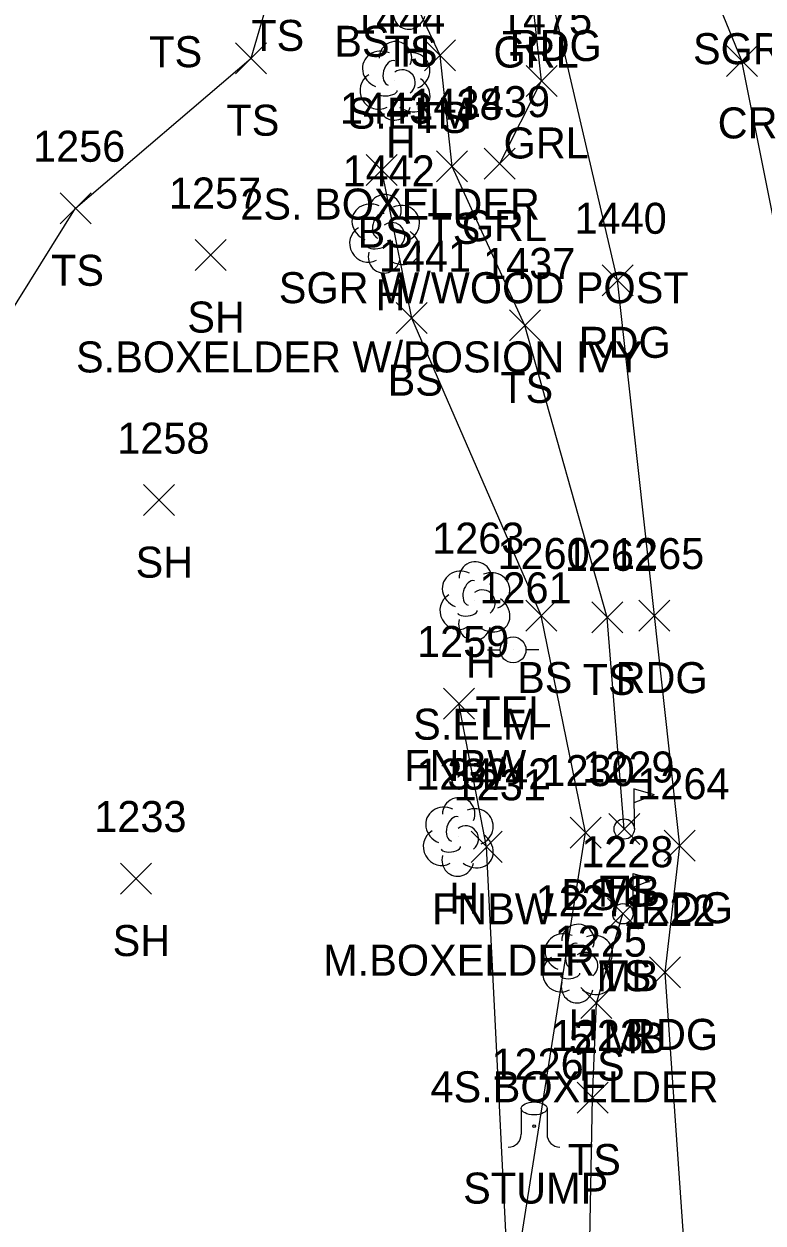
# Model space of a CAD drawing. Extents: x 1459992 to 1461532, y 647785 to 648535.
# Drawn here: x 1461337.5 to 1461385.2, y 648040.8 to 648118.2 of the extents above; entities that cross this region are included whole.
import ezdxf

# ---------------------------------------------------------------- set-up
doc = ezdxf.new("R2010")
doc.units = 0
for name, color, linetype in [('L_A', 7, 'Continuous'), ('L_C', 7, 'Continuous'), ('L_I', 7, 'Continuous'), ('L_TIC', 7, 'Continuous'), ('LELB', 7, 'Continuous'), ('LFNC', 7, 'Continuous'), ('LMB', 7, 'Continuous'), ('LTD', 7, 'Continuous'), ('LTS', 7, 'Continuous'), ('P_A', 7, 'Continuous'), ('P_I', 7, 'Continuous'), ('P_TIC', 7, 'Continuous'), ('PEU', 7, 'Continuous'), ('PRC', 7, 'Continuous'), ('R_A', 7, 'Continuous'), ('R_C', 7, 'Continuous'), ('R_I', 7, 'Continuous'), ('R_TIC', 7, 'Continuous'), ('RGR', 7, 'Continuous'), ('U_A', 7, 'Continuous'), ('U_C', 7, 'Continuous'), ('U_I', 7, 'Continuous'), ('UP', 7, 'Continuous')]:
    doc.layers.add(name, color=color, linetype=linetype)

msp = doc.modelspace()

# ---------------------------------------------------------------- linework, layer by layer
at = {"layer": 'L_TIC'}
for points in [[(1461351.192, 648114.964), (1461353.192, 648116.964)], [(1461353.192, 648114.964), (1461351.192, 648116.964)], [(1461363.389, 648115.139), (1461365.389, 648117.139)], [(1461365.389, 648115.139), (1461363.389, 648117.139)], [(1461359.617, 648107.744), (1461361.617, 648109.744)], [(1461361.617, 648107.744), (1461359.617, 648109.744)], [(1461364.162, 648107.989), (1461366.162, 648109.989)], [(1461366.162, 648107.989), (1461364.162, 648109.989)], [(1461339.87, 648105.284), (1461341.87, 648107.284)], [(1461341.87, 648105.284), (1461339.87, 648107.284)], [(1461348.586, 648102.268), (1461350.586, 648104.268)], [(1461350.586, 648102.268), (1461348.586, 648104.268)], [(1461361.563, 648098.199), (1461363.563, 648100.199)], [(1461363.563, 648098.199), (1461361.563, 648100.199)], [(1461368.859, 648097.73), (1461370.859, 648099.73)], [(1461370.859, 648097.73), (1461368.859, 648099.73)], [(1461345.25, 648086.46), (1461347.25, 648088.46)], [(1461347.25, 648086.46), (1461345.25, 648088.46)], [(1461369.917, 648079.019), (1461371.917, 648081.019)], [(1461371.917, 648079.019), (1461369.917, 648081.019)], [(1461374.178, 648078.9), (1461376.178, 648080.9)], [(1461376.178, 648078.9), (1461374.178, 648080.9)], [(1461364.601, 648073.344), (1461366.601, 648075.344)], [(1461366.601, 648073.344), (1461364.601, 648075.344)], [(1461372.77, 648065.017), (1461374.77, 648067.017)], [(1461374.77, 648065.017), (1461372.77, 648067.017)], [(1461375.265, 648065.249), (1461377.265, 648067.249)], [(1461377.265, 648065.249), (1461375.265, 648067.249)], [(1461366.388, 648064.1), (1461368.388, 648066.1)], [(1461368.388, 648064.1), (1461366.388, 648066.1)], [(1461343.768, 648062.055), (1461345.768, 648064.055)], [(1461345.768, 648062.055), (1461343.768, 648064.055)], [(1461375.185, 648059.787), (1461377.185, 648061.787)], [(1461377.185, 648059.787), (1461375.185, 648061.787)], [(1461373.473, 648054.018), (1461375.473, 648056.018)], [(1461375.473, 648054.018), (1461373.473, 648056.018)], [(1461373.225, 648047.932), (1461375.225, 648049.932)], [(1461375.225, 648047.932), (1461373.225, 648049.932)]]:
    msp.add_lwpolyline(points, dxfattribs=at)
at = {"layer": 'LELB'}
for points in [[(1461244.522, 647997.797), (1461264.749, 648013.285), (1461278.143, 648036.95), (1461298.413, 648049.424), (1461313.118, 648068.258), (1461328.135, 648085.894), (1461340.87, 648106.284), (1461352.192, 648115.964), (1461353.792, 648121.433), (1461352.841, 648127.816), (1461347.209, 648120.383), (1461340.274, 648126.529)], [(1461376.265, 648066.249), (1461375.178, 648079.9), (1461369.859, 648098.73), (1461365.162, 648108.989), (1461364.389, 648116.139), (1461362.394, 648120.42), (1461360.563, 648126.873)], [(1461374.676, 647991.798), (1461368.805, 648024.129), (1461368.877, 648035.126), (1461373.77, 648066.017), (1461370.917, 648080.019), (1461362.563, 648099.199), (1461360.617, 648108.744)], [(1461373.752, 648023.7), (1461374.225, 648048.932), (1461374.473, 648055.018), (1461376.185, 648060.787)]]:
    msp.add_lwpolyline(points, dxfattribs=at)
at = {"layer": 'LFNC'}
msp.add_lwpolyline([(1461368.877, 648035.126), (1461367.388, 648065.1), (1461365.601, 648074.344)], dxfattribs=at)
at = {"layer": 'LMB'}
for p, q in [((1461376.915, 648068.85), (1461378.209, 648068.468)), ((1461376.921, 648066.258), (1461376.92, 648068.852)), ((1461376.92, 648067.951), (1461378.203, 648068.459)), ((1461376.265, 648066.249), (1461376.265, 648066.249)), ((1461376.834, 648063.388), (1461378.128, 648063.006)), ((1461376.841, 648060.796), (1461376.839, 648063.39)), ((1461376.839, 648062.489), (1461378.122, 648062.997)), ((1461376.185, 648060.787), (1461376.185, 648060.787))]:
    msp.add_line(p, q, dxfattribs=at)
for centre in [(1461376.265, 648066.249), (1461376.184, 648060.787)]:
    msp.add_circle(centre, 0.656, dxfattribs=at)
at = {"layer": 'LTD'}
for p, q in [((1461361.46, 648114.554), (1461361.46, 648114.554)), ((1461361.46, 648114.554), (1461361.46, 648114.554)), ((1461360.786, 648104.696), (1461360.786, 648104.696)), ((1461360.786, 648104.696), (1461360.786, 648104.696)), ((1461366.615, 648081.009), (1461366.615, 648081.009)), ((1461366.615, 648081.009), (1461366.615, 648081.009)), ((1461365.543, 648065.79), (1461365.543, 648065.79)), ((1461365.543, 648065.79), (1461365.543, 648065.79)), ((1461373.242, 648057.624), (1461373.242, 648057.624)), ((1461373.242, 648057.624), (1461373.242, 648057.624))]:
    msp.add_line(p, q, dxfattribs=at)
for centre in [(1461361.507, 648115.988), (1461360.833, 648106.13), (1461366.662, 648082.443), (1461365.59, 648067.224), (1461373.289, 648059.058)]:
    msp.add_arc(centre, 1.047, 335.52715, 180.95627, dxfattribs=at)
for centre, major_axis, ratio, start_param, end_param in [((1461362.394, 648118.92), (0.265, 1.061), 0.942809, 1.570796, 4.712389), ((1461360.669, 648115.22), (1.21, -0.512), 0.895232, 1.570796, 4.712389), ((1461362.502, 648115.137), (-1.141, -0.483), 0.949671, 1.570796, 4.712389), ((1461361.252, 648115.012), (-0.208, -0.792), 0.645439, 3.141593, 6.283185), ((1461360.377, 648113.845), (0.584, -1.042), 0.959034, 3.141593, 6.283185), ((1461361.96, 648114.387), (-0.5, 0.667), 0.989748, 3.141593, 6.283185), ((1461362.46, 648113.721), (-1.09, 0.792), 0.841452, 1.570796, 4.712389), ((1461361.002, 648113.804), (-0.625, -0.083), 0.423636, 0, 3.141593), ((1461361.461, 648113.054), (0.265, 1.061), 0.942809, 1.570796, 4.712389), ((1461359.994, 648105.363), (1.21, -0.512), 0.895232, 1.570796, 4.712389), ((1461361.828, 648105.28), (-1.141, -0.483), 0.949671, 1.570796, 4.712389), ((1461360.578, 648105.154), (-0.208, -0.792), 0.645439, 3.141593, 6.283185), ((1461359.703, 648103.988), (0.584, -1.042), 0.959034, 3.141593, 6.283185), ((1461361.286, 648104.53), (-0.5, 0.667), 0.989748, 3.141593, 6.283185), ((1461361.786, 648103.863), (-1.09, 0.792), 0.841452, 1.570796, 4.712389), ((1461360.786, 648103.196), (0.265, 1.061), 0.942809, 1.570796, 4.712389), ((1461360.328, 648103.946), (-0.625, -0.083), 0.423636, 0, 3.141593), ((1461365.823, 648081.676), (1.21, -0.512), 0.895232, 1.570796, 4.712389), ((1461367.657, 648081.593), (-1.141, -0.483), 0.949671, 1.570796, 4.712389), ((1461366.407, 648081.468), (-0.208, -0.792), 0.645439, 3.141593, 6.283185), ((1461367.115, 648080.843), (-0.5, 0.667), 0.989748, 3.141593, 6.283185), ((1461365.532, 648080.301), (0.584, -1.042), 0.959034, 3.141593, 6.283185), ((1461367.615, 648080.176), (-1.09, 0.792), 0.841452, 1.570796, 4.712389), ((1461366.157, 648080.259), (-0.625, -0.083), 0.423636, 0, 3.141593), ((1461366.615, 648079.509), (0.265, 1.061), 0.942809, 1.570796, 4.712389), ((1461364.751, 648066.457), (1.21, -0.512), 0.895232, 1.570796, 4.712389), ((1461366.585, 648066.374), (-1.141, -0.483), 0.949671, 1.570796, 4.712389), ((1461365.335, 648066.249), (-0.208, -0.792), 0.645439, 3.141593, 6.283185), ((1461366.043, 648065.624), (-0.5, 0.667), 0.989748, 3.141593, 6.283185), ((1461364.46, 648065.082), (0.584, -1.042), 0.959034, 3.141593, 6.283185), ((1461366.543, 648064.957), (-1.09, 0.792), 0.841452, 1.570796, 4.712389), ((1461365.085, 648065.04), (-0.625, -0.083), 0.423636, 0, 3.141593), ((1461365.543, 648064.29), (0.265, 1.061), 0.942809, 1.570796, 4.712389), ((1461372.45, 648058.29), (1.21, -0.512), 0.895232, 1.570796, 4.712389), ((1461374.284, 648058.207), (-1.141, -0.483), 0.949671, 1.570796, 4.712389), ((1461373.034, 648058.082), (-0.208, -0.792), 0.645439, 3.141593, 6.283185), ((1461372.159, 648056.915), (0.584, -1.042), 0.959034, 3.141593, 6.283185), ((1461373.742, 648057.457), (-0.5, 0.667), 0.989748, 3.141593, 6.283185), ((1461374.242, 648056.791), (-1.09, 0.792), 0.841452, 1.570796, 4.712389), ((1461372.784, 648056.874), (-0.625, -0.083), 0.423636, 0, 3.141593), ((1461373.242, 648056.124), (0.265, 1.061), 0.942809, 1.570796, 4.712389)]:
    msp.add_ellipse(centre, major_axis=major_axis, ratio=ratio, start_param=start_param, end_param=end_param, dxfattribs=at)
at = {"layer": 'LTS'}
for p, q in [((1461369.622, 648048.23), (1461369.622, 648046.564)), ((1461371.289, 648048.064), (1461371.289, 648048.23)), ((1461371.289, 648048.23), (1461371.289, 648046.564)), ((1461370.455, 648047.088), (1461370.455, 648047.088)), ((1461370.455, 648047.088), (1461370.455, 648047.088)), ((1461370.455, 648047.064), (1461370.455, 648047.064))]:
    msp.add_line(p, q, dxfattribs=at)
msp.add_circle((1461370.455, 648047.088), 0.0833, dxfattribs=at)
for centre, start, end in [((1461368.789, 648046.564), 270, 360), ((1461372.122, 648046.564), 180, 270)]:
    msp.add_arc(centre, 0.833, start, end, dxfattribs=at)
msp.add_ellipse((1461370.455, 648048.23), major_axis=(-0.833, 0), ratio=0.5, dxfattribs=at)
at = {"layer": 'P_TIC'}
for points in [[(1461382.866, 648114.79), (1461384.866, 648116.79)], [(1461384.866, 648114.79), (1461382.866, 648116.79)], [(1461374.843, 648100.639), (1461376.843, 648102.639)], [(1461376.843, 648100.639), (1461374.843, 648102.639)], [(1461377.22, 648079.013), (1461379.22, 648081.013)], [(1461379.22, 648079.013), (1461377.22, 648081.013)], [(1461378.853, 648064.172), (1461380.853, 648066.172)], [(1461380.853, 648064.172), (1461378.853, 648066.172)], [(1461377.9, 648056.005), (1461379.9, 648058.005)], [(1461379.9, 648056.005), (1461377.9, 648058.005)]]:
    msp.add_lwpolyline(points, dxfattribs=at)
at = {"layer": 'PEU'}
msp.add_lwpolyline([(1461390.506, 647801.302), (1461390.529, 647837.718), (1461390.801, 647875.02), (1461390.064, 647897.408), (1461389.914, 647928.517), (1461386.454, 647961.517), (1461383.38, 647992.893), (1461381.214, 648023.996), (1461378.9, 648057.005), (1461379.853, 648065.172), (1461378.22, 648080.013), (1461375.843, 648101.639), (1461371.389, 648120.78), (1461367.19, 648133.394), (1461361.392, 648144.718), (1461357.891, 648149.467), (1461353.744, 648153.756)], dxfattribs=at)
at = {"layer": 'PRC'}
msp.add_lwpolyline([(1461399.102, 647801.607), (1461400.203, 647838.194), (1461399.73, 647875.765), (1461399.539, 647898.401), (1461398.446, 647928.211), (1461395.012, 647961.974), (1461394.123, 647993.813), (1461392.15, 648024.041), (1461390.381, 648057.367), (1461388.518, 648080.662), (1461387.016, 648100.033), (1461383.866, 648115.79), (1461378.351, 648129.267), (1461372.213, 648140.65), (1461365.441, 648150.969), (1461358.126, 648158.61)], dxfattribs=at)
at = {"layer": 'R_TIC'}
for points in [[(1461369.939, 648113.496), (1461371.939, 648115.496)], [(1461371.939, 648113.496), (1461369.939, 648115.496)], [(1461367.238, 648108.163), (1461369.238, 648110.163)], [(1461369.238, 648108.163), (1461367.238, 648110.163)]]:
    msp.add_lwpolyline(points, dxfattribs=at)
at = {"layer": 'RGR'}
msp.add_lwpolyline([(1461368.238, 648109.163), (1461370.939, 648114.496), (1461370.285, 648120.361), (1461365.964, 648132.75), (1461361.016, 648144.4), (1461357.68, 648149.267), (1461354.985, 648152.39), (1461353.744, 648153.756)], dxfattribs=at)
at = {"layer": 'UP'}
for p, q in [((1461367.438, 648077.797), (1461368.264, 648077.797)), ((1461369.097, 648077.802), (1461369.097, 648077.802)), ((1461370.764, 648077.802), (1461369.931, 648077.802)), ((1461369.931, 648077.802), (1461369.931, 648077.802)), ((1461370.764, 648077.802), (1461370.764, 648077.802))]:
    msp.add_line(p, q, dxfattribs=at)
msp.add_circle((1461369.097, 648077.802), 0.833, dxfattribs=at)

# ---------------------------------------------------------------- texts
at = {"layer": 'L_A'}
for s, p in [('TS', (1461352.201, 648116.433)), ('BS', (1461357.561, 648116.053)), ('TS', (1461345.618, 648115.383)), ('TS', (1461360.803, 648115.42)), ('H', (1461361.827, 648115.42)), ('TS', (1461350.601, 648110.964)), ('TS', (1461362.798, 648111.139)), ('H', (1461360.893, 648109.554)), ('BS', (1461359.058, 648103.744)), ('TS', (1461363.571, 648103.989)), ('TS', (1461339.28, 648101.284)), ('H', (1461360.219, 648099.696)), ('SH', (1461348.075, 648098.268)), ('BS', (1461361.004, 648094.199)), ('TS', (1461368.268, 648093.73)), ('SH', (1461344.738, 648082.46)), ('H', (1461366.048, 648076.009)), ('BS', (1461369.358, 648075.019)), ('TS', (1461373.588, 648074.9)), ('FNBW', (1461362.073, 648069.344)), ('TS', (1461374.675, 648061.249)), ('MB', (1461374.572, 648061.249)), ('H', (1461364.976, 648060.79)), ('BS', (1461372.211, 648061.017)), ('FNBW', (1461363.86, 648060.1)), ('SH', (1461343.256, 648058.055)), ('TS', (1461374.594, 648055.787)), ('MB', (1461374.492, 648055.787)), ('H', (1461372.675, 648052.624)), ('TS', (1461372.882, 648050.018)), ('TS', (1461372.634, 648043.932)), ('STUMP', (1461365.876, 648042.09))]:
    msp.add_text(s, height=2, dxfattribs=at).set_placement(p)
at = {"layer": 'L_C'}
for s, p in [('S.ELM', (1461358.425, 648111.42)), ('2S. BOXELDER', (1461351.5, 648105.554)), ('S.BOXELDER W/POSION IVY', (1461340.896, 648095.696)), ('S.ELM', (1461362.647, 648072.009)), ('M.BOXELDER', (1461356.842, 648056.79)), ('5 MB', (1461372.696, 648051.787)), ('4S.BOXELDER', (1461363.77, 648048.624))]:
    msp.add_text(s, height=2, dxfattribs=at).set_placement(p)
at = {"layer": 'L_I'}
for s, p in [('1444', (1461358.767, 648117.554)), ('1443', (1461357.924, 648111.744)), ('1438', (1461362.469, 648111.989)), ('1256', (1461338.122, 648109.284)), ('1442', (1461358.093, 648107.696)), ('1257', (1461346.893, 648106.268)), ('1441', (1461360.437, 648102.199)), ('1437', (1461367.166, 648101.73)), ('1258', (1461343.557, 648090.46)), ('1263', (1461363.875, 648084.009)), ('1260', (1461368.09, 648083.019)), ('1262', (1461372.438, 648082.9)), ('1259', (1461362.9, 648077.344)), ('1232', (1461362.85, 648068.79)), ('1230', (1461370.991, 648069.017)), ('1229', (1461373.564, 648069.249)), ('1229', (1461373.564, 648069.249)), ('1231', (1461365.262, 648068.1)), ('1233', (1461342.075, 648066.055)), ('1228', (1461373.492, 648063.787)), ('1228', (1461373.492, 648063.787)), ('1227', (1461370.549, 648060.624)), ('1225', (1461371.78, 648058.018)), ('1223', (1461371.532, 648051.932)), ('1226', (1461367.703, 648050.09))]:
    msp.add_text(s, height=2, dxfattribs=at).set_placement(p)
at = {"layer": 'P_A'}
for s, p in [('RDG', (1461368.877, 648115.78)), ('CR', (1461382.299, 648110.79)), ('RDG', (1461373.331, 648096.639)), ('RDG', (1461375.708, 648075.013)), ('RDG', (1461377.341, 648060.172)), ('RDG', (1461376.388, 648052.005))]:
    msp.add_text(s, height=2, dxfattribs=at).set_placement(p)
at = {"layer": 'P_I'}
for s, p in [('1440', (1461373.064, 648104.639)), ('1265', (1461375.48, 648083.013)), ('1264', (1461377.113, 648068.172)), ('1222', (1461376.207, 648060.005))]:
    msp.add_text(s, height=2, dxfattribs=at).set_placement(p)
at = {"layer": 'R_A'}
for p in [(1461367.828, 648115.361), (1461368.482, 648109.496), (1461365.781, 648104.163)]:
    msp.add_text('GRL', height=2, dxfattribs=at).set_placement(p)
at = {"layer": 'R_C'}
for p in [(1461380.706, 648115.578), (1461353.978, 648100.163)]:
    msp.add_text('SGR W/WOOD POST', height=2, dxfattribs=at).set_placement(p)
at = {"layer": 'R_I'}
for s, p in [('1475', (1461368.246, 648117.496)), ('1439', (1461365.537, 648112.163))]:
    msp.add_text(s, height=2, dxfattribs=at).set_placement(p)
at = {"layer": 'U_A'}
msp.add_text('TEL', height=2, dxfattribs=at).set_placement((1461366.656, 648072.802))
at = {"layer": 'U_C'}
msp.add_text('34/42', height=2, dxfattribs=at).set_placement((1461364.861, 648068.802))
at = {"layer": 'U_I'}
msp.add_text('1261', height=2, dxfattribs=at).set_placement((1461366.924, 648080.802))

doc.saveas('drawing.dxf')
